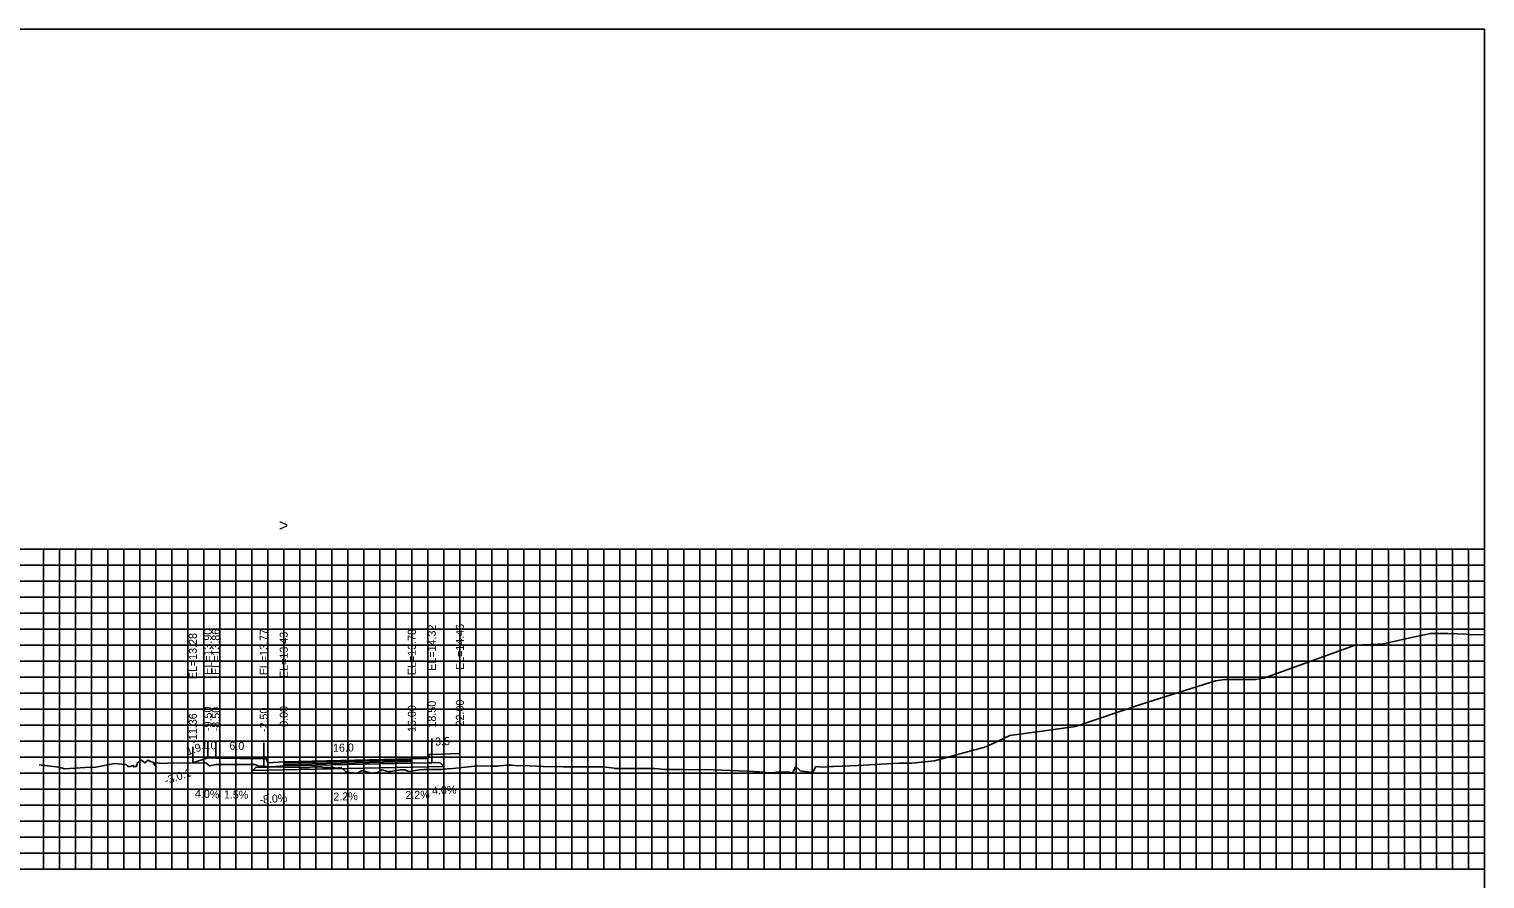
# Model space of a CAD drawing. Extents: x 1797645 to 1803805, y 248417 to 250269.
# Drawn here: x 1802939.2 to 1803121.1, y 250163.2 to 250269.4 of the extents above; entities that cross this region are included whole.
import ezdxf

# ---------------------------------------------------------------- set-up
doc = ezdxf.new("R2010")
doc.units = 0
for name, color, linetype in [('3', 7, 'Continuous'), ('4', 7, 'Continuous'), ('60', 7, 'Continuous'), ('BASE', 7, 'Continuous'), ('CL-CNST', 7, 'Continuous'), ('Level 62', 7, 'Continuous'), ('LOWER BINDER', 7, 'Continuous'), ('M-ROADS', 7, 'Continuous'), ('UPPER BINDER', 7, 'Continuous'), ('WEARING', 7, 'Continuous')]:
    doc.layers.add(name, color=color, linetype=linetype)

msp = doc.modelspace()

# ---------------------------------------------------------------- linework, layer by layer
for p, q in [((1802959.64, 250177.71), (1802959.64, 250179.71)), ((1802961.5, 250178.33), (1802961.5, 250180.33)), ((1802962.5, 250178.29), (1802962.5, 250180.29)), ((1802968.5, 250178.2), (1802968.5, 250180.2)), ((1802968.5, 250178.2), (1802968.5, 250180.2)), ((1802971, 250177.86), (1802971, 250179.86)), ((1802987, 250178.21), (1802987, 250180.21)), ((1802989.5, 250178.75), (1802989.5, 250180.75)), ((1802993, 250178.89), (1802993, 250180.89))]:
    msp.add_line(p, q)
for points in [[(1802821, 250079.43), (1803121, 250079.43), (1803121, 250269.43), (1802821, 250269.43)], [(1802971, 250177.86), (1802969, 250177.7), (1802968.83, 250178.2), (1802968.5, 250178.2), (1802968.5, 250177.17), (1802969, 250177.17), (1802971, 250177.33)], [(1802987, 250178.21), (1802989, 250178.25), (1802989.17, 250178.75), (1802989.5, 250178.75), (1802989.5, 250177.72), (1802989, 250177.72), (1802987, 250177.68)]]:
    msp.add_lwpolyline(points, close=True)
at = {"layer": '60'}
for p, q in [((1803121, 250164.43), (1803121, 250204.43)), ((1803121.06, 250204.43), (1803121, 250204.43)), ((1803121.06, 250194.43), (1803121, 250194.43)), ((1803121.06, 250184.43), (1803121, 250184.43)), ((1803121.06, 250174.43), (1803121, 250174.43)), ((1802821, 250164.43), (1803121, 250164.43)), ((1802941, 250164.37), (1802941, 250164.43)), ((1802951, 250164.37), (1802951, 250164.43)), ((1802961, 250164.37), (1802961, 250164.43)), ((1802971, 250164.37), (1802971, 250164.43)), ((1802981, 250164.37), (1802981, 250164.43)), ((1802991, 250164.37), (1802991, 250164.43)), ((1803001, 250164.37), (1803001, 250164.43)), ((1803011, 250164.37), (1803011, 250164.43)), ((1803021, 250164.37), (1803021, 250164.43)), ((1803031, 250164.37), (1803031, 250164.43)), ((1803041, 250164.37), (1803041, 250164.43)), ((1803051, 250164.37), (1803051, 250164.43)), ((1803061, 250164.37), (1803061, 250164.43)), ((1803071, 250164.37), (1803071, 250164.43)), ((1803081, 250164.37), (1803081, 250164.43)), ((1803091, 250164.37), (1803091, 250164.43)), ((1803101, 250164.37), (1803101, 250164.43)), ((1803111, 250164.37), (1803111, 250164.43)), ((1803121, 250164.37), (1803121, 250164.43)), ((1803121.06, 250164.43), (1803121, 250164.43))]:
    msp.add_line(p, q, dxfattribs=at)
at = {"layer": 'BASE'}
msp.add_lwpolyline([(1802971, 250177.33), (1802987, 250177.68), (1802989, 250177.72), (1802989.5, 250177.72), (1802990.5, 250177.75), (1802990.98, 250177.27), (1802987, 250177.18), (1802971, 250176.83), (1802967.09, 250176.74), (1802967.5, 250177.15), (1802968.5, 250177.17), (1802969, 250177.17)], close=True, dxfattribs=at)
at = {"layer": 'CL-CNST'}
msp.add_lwpolyline([(1802959.64, 250177.71), (1802961.5, 250178.33), (1802962.5, 250178.29), (1802968.5, 250178.2), (1802968.5, 250178.2), (1802968.83, 250178.2), (1802969, 250177.7), (1802971, 250177.86), (1802987, 250178.21), (1802989, 250178.25), (1802989.17, 250178.75), (1802989.5, 250178.75), (1802993, 250178.89)], dxfattribs=at)
at = {"layer": 'Level 62'}
for p, q in [((1802821, 250204.43), (1803121, 250204.43)), ((1802941, 250164.43), (1802941, 250204.43)), ((1802943, 250164.43), (1802943, 250204.43)), ((1802945, 250164.43), (1802945, 250204.43)), ((1802947, 250164.43), (1802947, 250204.43)), ((1802949, 250164.43), (1802949, 250204.43)), ((1802951, 250164.43), (1802951, 250204.43)), ((1802953, 250164.43), (1802953, 250204.43)), ((1802955, 250164.43), (1802955, 250204.43)), ((1802957, 250164.43), (1802957, 250204.43)), ((1802959, 250164.43), (1802959, 250204.43)), ((1802961, 250164.43), (1802961, 250204.43)), ((1802963, 250164.43), (1802963, 250204.43)), ((1802965, 250164.43), (1802965, 250204.43)), ((1802967, 250164.43), (1802967, 250204.43)), ((1802969, 250164.43), (1802969, 250204.43)), ((1802971, 250164.43), (1802971, 250204.43)), ((1802973, 250164.43), (1802973, 250204.43)), ((1802975, 250164.43), (1802975, 250204.43)), ((1802977, 250164.43), (1802977, 250204.43)), ((1802979, 250164.43), (1802979, 250204.43)), ((1802981, 250164.43), (1802981, 250204.43)), ((1802983, 250164.43), (1802983, 250204.43)), ((1802985, 250164.43), (1802985, 250204.43)), ((1802987, 250164.43), (1802987, 250204.43)), ((1802989, 250164.43), (1802989, 250204.43)), ((1802991, 250164.43), (1802991, 250204.43)), ((1802993, 250164.43), (1802993, 250204.43)), ((1802995, 250164.43), (1802995, 250204.43)), ((1802997, 250164.43), (1802997, 250204.43)), ((1802999, 250164.43), (1802999, 250204.43)), ((1803001, 250164.43), (1803001, 250204.43)), ((1803003, 250164.43), (1803003, 250204.43)), ((1803005, 250164.43), (1803005, 250204.43)), ((1803007, 250164.43), (1803007, 250204.43)), ((1803009, 250164.43), (1803009, 250204.43)), ((1803011, 250164.43), (1803011, 250204.43)), ((1803013, 250164.43), (1803013, 250204.43)), ((1803015, 250164.43), (1803015, 250204.43)), ((1803017, 250164.43), (1803017, 250204.43)), ((1803019, 250164.43), (1803019, 250204.43)), ((1803021, 250164.43), (1803021, 250204.43)), ((1803023, 250164.43), (1803023, 250204.43)), ((1803025, 250164.43), (1803025, 250204.43)), ((1803027, 250164.43), (1803027, 250204.43)), ((1803029, 250164.43), (1803029, 250204.43)), ((1803031, 250164.43), (1803031, 250204.43)), ((1803033, 250164.43), (1803033, 250204.43)), ((1803035, 250164.43), (1803035, 250204.43)), ((1803037, 250164.43), (1803037, 250204.43)), ((1803039, 250164.43), (1803039, 250204.43)), ((1803041, 250164.43), (1803041, 250204.43)), ((1803043, 250164.43), (1803043, 250204.43)), ((1803045, 250164.43), (1803045, 250204.43)), ((1803047, 250164.43), (1803047, 250204.43)), ((1803049, 250164.43), (1803049, 250204.43)), ((1803051, 250164.43), (1803051, 250204.43)), ((1803053, 250164.43), (1803053, 250204.43)), ((1803055, 250164.43), (1803055, 250204.43)), ((1803057, 250164.43), (1803057, 250204.43)), ((1803059, 250164.43), (1803059, 250204.43)), ((1803061, 250164.43), (1803061, 250204.43)), ((1803063, 250164.43), (1803063, 250204.43)), ((1803065, 250164.43), (1803065, 250204.43)), ((1803067, 250164.43), (1803067, 250204.43)), ((1803069, 250164.43), (1803069, 250204.43)), ((1803071, 250164.43), (1803071, 250204.43)), ((1803073, 250164.43), (1803073, 250204.43)), ((1803075, 250164.43), (1803075, 250204.43)), ((1803077, 250164.43), (1803077, 250204.43)), ((1803079, 250164.43), (1803079, 250204.43)), ((1803081, 250164.43), (1803081, 250204.43)), ((1803083, 250164.43), (1803083, 250204.43)), ((1803085, 250164.43), (1803085, 250204.43)), ((1803087, 250164.43), (1803087, 250204.43)), ((1803089, 250164.43), (1803089, 250204.43)), ((1803091, 250164.43), (1803091, 250204.43)), ((1803093, 250164.43), (1803093, 250204.43)), ((1803095, 250164.43), (1803095, 250204.43)), ((1803097, 250164.43), (1803097, 250204.43)), ((1803099, 250164.43), (1803099, 250204.43)), ((1803101, 250164.43), (1803101, 250204.43)), ((1803103, 250164.43), (1803103, 250204.43)), ((1803105, 250164.43), (1803105, 250204.43)), ((1803107, 250164.43), (1803107, 250204.43)), ((1803109, 250164.43), (1803109, 250204.43)), ((1803111, 250164.43), (1803111, 250204.43)), ((1803113, 250164.43), (1803113, 250204.43)), ((1803115, 250164.43), (1803115, 250204.43)), ((1803117, 250164.43), (1803117, 250204.43)), ((1803119, 250164.43), (1803119, 250204.43)), ((1803121, 250164.43), (1803121, 250204.43)), ((1802821, 250202.43), (1803121, 250202.43)), ((1802821, 250200.43), (1803121, 250200.43)), ((1802821, 250198.43), (1803121, 250198.43)), ((1802821, 250196.43), (1803121, 250196.43)), ((1802821, 250194.43), (1803121, 250194.43)), ((1802821, 250192.43), (1803121, 250192.43)), ((1802821, 250190.43), (1803121, 250190.43)), ((1802821, 250188.43), (1803121, 250188.43)), ((1802821, 250186.43), (1803121, 250186.43)), ((1802821, 250184.43), (1803121, 250184.43)), ((1802821, 250182.43), (1803121, 250182.43)), ((1802821, 250180.43), (1803121, 250180.43)), ((1802821, 250178.43), (1803121, 250178.43)), ((1802821, 250176.43), (1803121, 250176.43)), ((1802821, 250174.43), (1803121, 250174.43)), ((1802821, 250172.43), (1803121, 250172.43)), ((1802821, 250170.43), (1803121, 250170.43)), ((1802821, 250168.43), (1803121, 250168.43)), ((1802821, 250166.43), (1803121, 250166.43)), ((1802821, 250164.43), (1803121, 250164.43))]:
    msp.add_line(p, q, dxfattribs=at)
at = {"layer": 'LOWER BINDER'}
msp.add_lwpolyline([(1802987, 250177.68), (1802987, 250177.68), (1802987, 250177.87), (1802971, 250177.52), (1802971, 250177.33)], close=True, dxfattribs=at)
at = {"layer": 'M-ROADS'}
msp.add_lwpolyline([(1802940.44, 250177.46), (1802942.9, 250177.17), (1802943.64, 250176.97), (1802946.83, 250177.16), (1802947.33, 250177.15), (1802949.87, 250177.62), (1802951.26, 250177.49), (1802951.54, 250177.24), (1802951.57, 250177.24), (1802951.68, 250177.24), (1802951.76, 250177.24), (1802952.22, 250177.38), (1802952.25, 250177.2), (1802952.39, 250177.24), (1802952.57, 250177.27), (1802952.59, 250177.26), (1802952.6, 250177.41), (1802952.61, 250177.28), (1802952.71, 250177.73), (1802953.23, 250178.05), (1802953.65, 250177.72), (1802954.05, 250178.05), (1802954.34, 250177.88), (1802954.67, 250177.81), (1802954.83, 250177.41), (1802954.91, 250177.76), (1802955.79, 250177.62), (1802956.48, 250177.66), (1802961.25, 250177.73), (1802961.73, 250177.34), (1802962.54, 250177.49), (1802962.58, 250177.49), (1802964.94, 250177.49), (1802967.31, 250177.49), (1802967.44, 250177.49), (1802967.76, 250177.33), (1802969.03, 250177.26), (1802969.24, 250177.23), (1802969.32, 250177.22), (1802969.42, 250177.22), (1802972.85, 250177.13), (1802973.03, 250177.13), (1802973.18, 250177.13), (1802973.54, 250177.15), (1802974.16, 250177.13), (1802974.63, 250177.2), (1802975.75, 250177.2), (1802975.85, 250177.12), (1802976.46, 250177.13), (1802977.24, 250177.13), (1802977.46, 250177.07), (1802977.79, 250177.08), (1802978.04, 250177.08), (1802978.11, 250177.06), (1802978.18, 250177.15), (1802978.71, 250176.64), (1802979.39, 250176.46), (1802979.44, 250176.41), (1802979.56, 250176.53), (1802979.81, 250176.41), (1802980.18, 250176.41), (1802980.79, 250176.74), (1802981.62, 250176.52), (1802981.86, 250176.41), (1802982.7, 250176.5), (1802983.26, 250176.84), (1802984, 250176.64), (1802984.23, 250176.63), (1802984.3, 250176.64), (1802985.56, 250176.85), (1802986.12, 250176.85), (1802986.62, 250176.65), (1802988.05, 250176.85), (1802988.5, 250176.9), (1802990.66, 250176.9), (1802991.41, 250176.95), (1802992.13, 250177.02), (1802995.26, 250177.33), (1802996.82, 250177.32), (1802997.38, 250177.32), (1802997.48, 250177.32), (1802997.7, 250177.32), (1802998.01, 250177.33), (1802998.93, 250177.41), (1802999.52, 250177.44), (1803000.26, 250177.33), (1803000.8, 250177.37), (1803003.46, 250177.27), (1803005.96, 250177.22), (1803007.43, 250177.21), (1803008.48, 250177.21), (1803009.1, 250177.21), (1803010.96, 250177.22), (1803012.27, 250177.04), (1803012.3, 250177.03), (1803012.34, 250177.03), (1803014.81, 250177.03), (1803017.28, 250177.03), (1803017.33, 250177.03), (1803017.38, 250177.02), (1803018.55, 250176.88), (1803019.61, 250176.89), (1803021.08, 250176.87), (1803021.27, 250176.86), (1803023.55, 250176.88), (1803028.88, 250176.66), (1803030.44, 250176.6), (1803031.65, 250176.46), (1803032.06, 250176.48), (1803032.61, 250176.54), (1803032.98, 250176.59), (1803033.46, 250176.54), (1803034.17, 250176.56), (1803034.51, 250176.46), (1803034.58, 250176.56), (1803034.99, 250177.24), (1803035.5, 250176.73), (1803036.67, 250176.56), (1803036.72, 250176.55), (1803036.91, 250176.53), (1803037.08, 250176.56), (1803037.49, 250177.24), (1803038.29, 250177.17), (1803039.42, 250177.24), (1803039.7, 250177.26), (1803042.68, 250177.39), (1803047.89, 250177.66), (1803048.67, 250177.66), (1803049.46, 250177.66), (1803052.32, 250177.97), (1803058.7, 250179.7), (1803061.71, 250181.12), (1803065.37, 250181.63), (1803065.4, 250181.63), (1803065.43, 250181.63), (1803069.91, 250182.28), (1803078.16, 250185.07), (1803087.42, 250187.96), (1803088.57, 250188.12), (1803090.47, 250188.12), (1803092.37, 250188.12), (1803093.43, 250188.3), (1803104.85, 250192.41), (1803107.66, 250192.55), (1803107.92, 250192.55), (1803108.18, 250192.55), (1803111.9, 250193.38), (1803114.25, 250193.9), (1803115.33, 250193.9), (1803116.42, 250193.9), (1803118.74, 250193.82), (1803119.45, 250193.73), (1803121, 250193.78)], dxfattribs=at)
at = {"layer": 'UPPER BINDER'}
msp.add_lwpolyline([(1802987, 250177.87), (1802987, 250178.06), (1802971, 250177.71), (1802971, 250177.52)], close=True, dxfattribs=at)
at = {"layer": 'WEARING'}
msp.add_lwpolyline([(1802987, 250178.06), (1802987, 250178.21), (1802971, 250177.86), (1802971, 250177.71)], close=True, dxfattribs=at)

# ---------------------------------------------------------------- texts
msp.add_text('-3.0:1', height=1, rotation=18.4349).set_placement((1802956.29, 250175))
at = {"layer": '3'}
for s, p in [('EL=13.90', (1802962, 250188.72)), ('EL=13.86', (1802963, 250188.71)), ('EL=13.77', (1802969, 250188.67)), ('EL=13.77', (1802969, 250188.67)), ('EL=13.43', (1802971.5, 250188.33)), ('EL=13.78', (1802987.5, 250188.68)), ('EL=14.32', (1802990, 250189.23)), ('EL=14.46', (1802993.5, 250189.32)), ('EL=13.28', (1802960.14, 250188.18)), ('16.00', (1802987.5, 250181.58)), ('18.50', (1802990, 250182.13)), ('22.00', (1802993.5, 250182.27)), ('-11.36', (1802960.14, 250180.12)), ('-9.50', (1802962, 250181.7)), ('-8.50', (1802963, 250181.66)), ('-2.50', (1802969, 250181.57)), ('-2.50', (1802969, 250181.57)), ('0.00', (1802971.5, 250182.22))]:
    msp.add_text(s, height=1, rotation=90, dxfattribs=at).set_placement(p)
at = {"layer": '4'}
for s, rotation, p in [('1.9', 18.4349, (1802959.01, 250178.66)), ('1.0', 357.7094, (1802960.72, 250179.46)), ('6.0', 359.1406, (1802964.2, 250179.36)), ('16.0', 1.2603, (1802977.16, 250179.09)), ('3.5', 2.2906, (1802989.92, 250179.87)), ('4.0%', 357.7094, (1802959.89, 250173.39)), ('1.5%', 359.1406, (1802963.51, 250173.27)), ('2.2%', 1.2603, (1802977.2, 250172.99)), ('2.2%', 1.2603, (1802986.2, 250173.19)), ('4.0%', 2.2906, (1802989.54, 250173.75)), ('-8.0%', 4.5739, (1802968, 250172.6))]:
    msp.add_text(s, height=1, rotation=rotation, dxfattribs=at).set_placement(p)
at = {"layer": '60'}
msp.add_text('>', height=1.5, dxfattribs=at).set_placement((1802970.39, 250206.68))

doc.saveas('drawing.dxf')
